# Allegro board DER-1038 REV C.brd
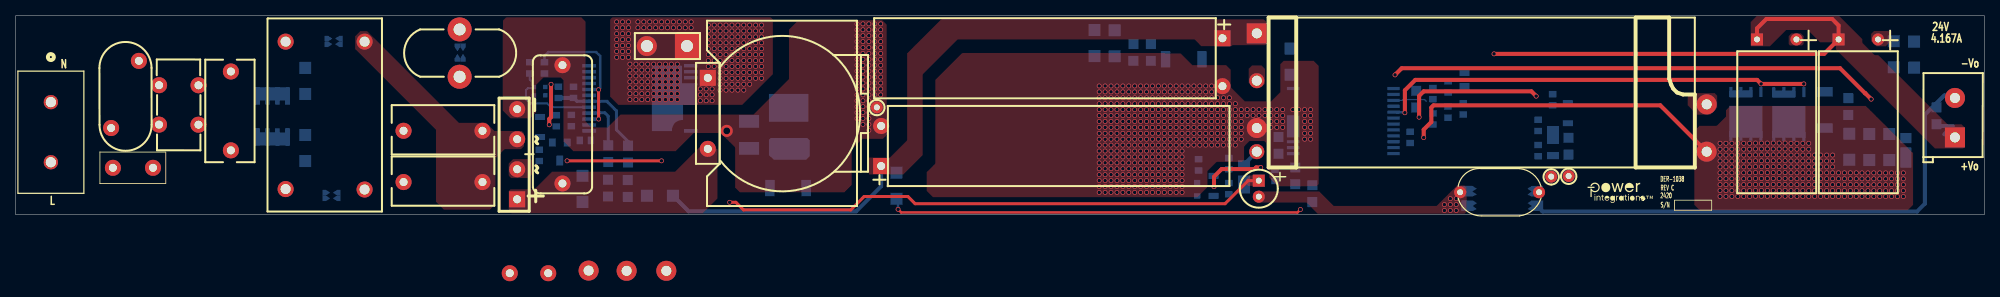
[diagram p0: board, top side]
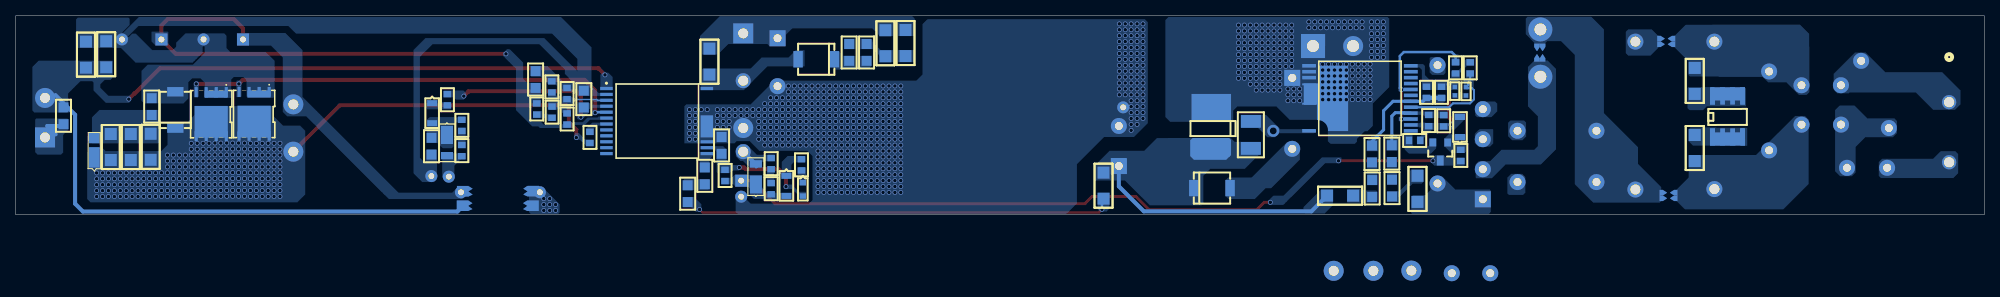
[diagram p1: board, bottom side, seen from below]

Outline 249.4 x 25.2 mm; copper layers: TOP, BOTTOM. Coordinates in mm from the lower left corner of the outline.
Outline path: 0,25.2 0,0 249.4,0 249.4,25.2 0,25.2

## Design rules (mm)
constraint set DEFAULT: min track width 0.508

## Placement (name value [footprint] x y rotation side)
BR1  UD4KB100-BP  [PIDAXBRIDGED3K]  63.53 1.93 90 top
C1  0.15 uF  [PINPXCAPRAD13X6MM040]  27.25 18.14 270 top
C2  0.15 uF  [PINPXCAPRAD13X6MM040]  59.13 10.62 180 top
C3  1 uF  [PINPCAPRAD17P5X7P8X15MMLS]  69.27 3.94 90 top
C4  1 uF  [PISMC0603]  72.87 9.4 180 bottom
C5  470 pF  [PISMC0603]  70.38 12.62 270 bottom
C6  1 uF  [PISMC0603]  66.98 19.3 270 bottom
C7  0.1 uF  [PISMC0603]  65.13 17.88 90 bottom
C8  1 uF  [PISMR0402]  67.08 15.11 90 bottom
C9  470 pF  [PISMC0603]  70.66 14.78 90 bottom
C10  22 nF  [PISMC1210]  92.91 8.38 90 bottom
C11  33 uF  [PIPOLCAPD395LS200D0401705LH]  153.59 22.35 270 top
C12  33 uF  [PIPOLCAPD395LS200D0401705LH#2]  108.94 6.15 90 top
C13  NC  [PISMC0603]  153.7 2.57 90 bottom
C14  22 uf  [PI_POLCAP_D200_LS80_D030]  157.49 4.29 270 top
C15  2.2 nF  [PISMC1206]  139.22 23.37 270 bottom
C16  0.47 uF  [PISMC0805]  159.98 7.7 90 bottom
C18  2.2 uF  [PISMC0805]  177.43 13.56 90 bottom
C19  2200 pF  [PINPCAPRAD11X6MMD030]  183 2.82 0 top
C20  NC  [PISMC0603]  192.89 7.39 90 bottom
C21  2200 pf  [PISMC0805]  232.18 14.76 270 bottom
C22  10 uF  [PISMC0805]  196.72 9.73 270 bottom
C23  22 nF  [PISMC0603]  181.46 12.27 90 bottom
C24  1 nF  [PISMC0603]  179.55 14.63 90 bottom
C25  680 uF  [PIPOLCAPCLYD10MMD30]  225.61 22.2 180 top
C26  680 uF  [PIPOLCAPCLYD10MMD30]  235.95 22.2 180 top
C27  2.2 uF  [PISMC0805]  243.36 11.46 90 bottom
C28  0.15 uF  [PINPXCAPRAD13X6MM040]  59.13 4.11 180 top
C29  47 pF  [PISMC1206]  161.52 21.03 270 bottom
C30  2.2 uF  [PISMC0805]  183.54 18.19 270 bottom
D1  LXA03D530  [PI_SM_DIODE_SO8C]  95.81 13.39 0 bottom
D3  STTH208UFY  [PISMDO221AA]  97.84 3.35 180 bottom
D4  DFLR1200-7  [PISMDDFLR120012]  155.63 3.78 270 bottom
D5  BAV19WS  [PISMSOD323]  151.76 4.9 270 bottom
D6  GS1MFL-TP  [PISMDO221AA]  147.98 19.68 0 bottom
D8  SS10200HE_R1_00001  [PI_SM_SOD-123HE]  239.47 7.24 90 bottom
D9  DFLR1200-7  [PISMDDFLR120012]  194.77 10.11 90 bottom
D10  BAV19WS  [PISMSOD323]  196.65 14.12 270 bottom
F1  3.15 A  [PI_RST_MICROFUSE]  12.31 5.92 0 top
FL1  Hole_30mils  [PI_HOLE_30MIL]  194.54 4.8 0 top
FL2  Hole_30mils  [PI_HOLE_30MIL]  196.75 4.88 0 top
FL3  Hole_30mils  [PI_HOLE_30MIL]  109.09 13.59 0 top
J1  TERMINAL BLOCK  [PI_TERM_BLOCK_2PIN_LS200]  245.69 9.78 0 top
J2  CON2  [CONN_1707027_PXC]  4.45 14.25 270 top
L1  330 uH  [PI_4P_LS5W4P8XD11P5MMD40]  20.65 13.89 269.9 top
L2  15 mH  [PIIND4P965X571LS736X394D040]  44.2 21.92 270 top
L3  68 uH  [PI2P14DX6MMWD060]  56.24 23.47 270 top
NOREF  -  []  249.4 0 90 top
NOREF#2  -  []  -150.23 13.59 0 top
NOREF#3  -  []  0 25.2 0 top
NOREF#4  -  []  198.73 3.28 0 top
NOREF#5  -  []  -232.77 -144.45 0 top
NOREF#6  -  [unnamed#2]  188.31 2.95 179.9 bottom
NOREF#7  -  [unnamed#2]  188.33 1.12 180 bottom
Q1  MMBT4401LT1G  [PISMSOT23123_1]  68.91 8.03 0 bottom
Q2  SRT15N110LD56TR-G  [PISMPQFN5X6B]  222.73 15.52 0 bottom
Q3  SRT15N110LD56TR-G  [PISMPQFN5X6B]  217.3 15.54 0 bottom
R1  510 k  [PISMR1206]  36.68 6.78 90 bottom
R2  510 k  [PISMR1206]  36.68 15.29 90 bottom
R3  100 K  [PISMR0603]  66.32 6.78 90 bottom
R4  6.8 M  [PISMR1206]  71.81 4.9 270 bottom
R5  4.7 M  [PISMR0805]  75.03 4.42 270 bottom
R6  4.7 M  [PISMR0805]  75.06 6.65 90 bottom
R7  154 k  [PISMR0603]  68.48 12.6 270 bottom
R8  30.1 k  [PISMR0402]  65.66 16.15 270 bottom
R9  6.8 M  [PISMR1206]  83.26 2.39 180 bottom
R10  4.7 M  [PISMR0805]  77.55 2.24 90 bottom
R11  4.7 M  [PISMR0805]  77.57 8.74 270 bottom
R12  158 k  [PISMR0603]  68.76 16.21 270 bottom
R13  NC  [PISMR0603]  153.7 5.74 90 bottom
R14  5.1 k  [PISMR0603]  159.54 4.24 90 bottom
R15  100  [PISMR0603]  149.86 5.59 90 bottom
R16  500 k  [PISMR1206]  136.68 23.39 270 bottom
R17  15  [PISMR0805]  143.81 19.48 90 bottom
R19  15  [PISMR0805]  141.6 19.48 90 bottom
R20  1.6 M  [PISMR1206]  111.58 5.31 270 bottom
R21  1.2 M  [PISMR0805]  164.27 1.57 90 bottom
R22  1.2 M  [PISMR0805]  162.1 3.84 90 bottom
R23  300  [PISMR0603]  176.66 9.07 90 bottom
R24  15  [PISMR1206]  234.82 10.21 270 bottom
R25  15  [PISMR1206]  232.31 10.24 270 bottom
R26  NC  [PISMR0603]  192.89 10.59 90 bottom
R27  4.7 k  [PISMR0603]  183.39 14.1 270 bottom
R28  1.2 k  [PISMR0603]  194.72 13.84 90 bottom
R29  100 K  [PISMR0603]  179.55 11.4 90 bottom
R30  5.49 k  [PISMR0603]  181.48 15.47 90 bottom
R31  0.01  [PISMR1206]  240.51 21.92 270 bottom
R32  0.01  [PISMR1206]  237.95 21.97 270 bottom
R33  15  [PISMR1206]  237.36 10.21 270 bottom
RV1  320 Vac  [PIDISC500X225LS335X140040]  15.6 19.48 270.1 top
T1  ATQ23.2/11.6  [PI_BOBBIN_ATQ23_V_4PB]  97.08 12.83 0 top
T2  EDR4110  [PI_BOBBIN_EDR4110_9P_6X3]  185.73 15.47 0 top
TAB1  CON2  [PI_CONN_QC_TAB_2PIN_LS200]  85.04 21.36 90 top
U1  CAP200DG *  [PI_IC_SMD_SO8_CAPZERO]  34.42 9.83 179.9 bottom
U2  PFS7624C  [PI_IC_INSOP24B]  79.1 14.73 0 bottom
U3  INN4276C-H182  [PI_IC_INSOP_24D_IPC]  174.56 15.98 180 bottom
VR1  BZX384-B13,115  [PISMSOD323]  66.42 9.83 90 bottom
VR2  DZ2S300M0L  [PI_SM_D_SSMINI2P]  149.68 4.04 270 bottom
VR3  SMA6F100A-M3/H  [PISMDO221AA]  229.18 13.26 90 bottom

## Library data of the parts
BR1 = DISCRETE BRIDGE_+~~-: alternate symbols: (pidaxbridgeD3K_horz)
C1 C2 C28 = CAP NP: alternate symbols: (pinpxcaprad13x6x12Hmm040); room: 1
C3 = CAP NP: alternate symbols: (pinpcaprad17p5x15mmLSH)
C4 C6 = CAP NP: alternate symbols: (Unisem_RMCF0603UL); room: 2
C5 C9 = CAP NP: room: 2
C7 = CAP NP: alternate symbols: (Unisem_RMCF0603UL,cc0603); room: 2
C8 = CAP NP: alternate symbols: (pismr0402_1); room: 2
C10 C19 C29 = CAP NP
C11 C12 C14 = CAP POL
C13 C20 = CAP NP: alternate symbols: (Unisem_RMCF0603UL)
C15 = CAP NP: alternate symbols: (CAP_3216_TDK); room: 3
C16 = CAP NP: alternate symbols: (Unisem_RMCF0805UL); room: 3
C18 C30 = CAP NP: room: 4
C21 = CAP NP: alternate symbols: (Unisem_RMCF0805UL); room: 4
C22 C27 = CAP NP: alternate symbols: (Unisem_RMCF0805UL)
C23 C24 = CAP NP: alternate symbols: (Unisem_RMCF0603UL); room: 4
C25 C26 = CAP POL: alternate symbols: (pipolcapclyd10x18mmD30H); room: 4
D1 = DIODE_A1K8
D3 = DIODE: room: 2
D4-D6 D9 D10 = DIODE
D8 = DIODE SCHOTTKY
F1 = FUSE: alternate symbols: (pirstmicrofusehoz); room: 1
FL1-FL3 = FlyingLead: room: 3
J1 = CON2
J2 = CON2: User Part Number: PN; Tolerance: TOL
L1 = TORRID 4P_14_23
L2 = INDUCTOR_4P_1-2_4-3
L3 = INDUCTOR: room: 1
Q1 = NPN_BEC: room: 2
Q2 Q3 = FET_N_SGD_123_4_5678
R1 R2 R16 R31 R32 = R
R3 R4 R8 R9 = R: room: 2
R5 R6 R10 R11 = R: alternate symbols: (Unisem_RMCF0805UL); room: 2
R7 R12 = R: alternate symbols: (Unisem_RMCF0603UL); room: 2
R13 R15 R26 = R: alternate symbols: (Unisem_RMCF0603UL)
R14 = R: alternate symbols: (Unisem_RMCF0603UL); room: 3
R17 R19 = R: alternate symbols: (Unisem_RMCF0805UL)
R20 = R: room: 3
R21 R22 = R: alternate symbols: (Unisem_RMCF0805UL); room: 3
R23 R27 R28 R30 = R: alternate symbols: (Unisem_RMCF0603UL); room: 4
R24 R25 R29 R33 = R: room: 4
RV1 = VARISTOR: alternate symbols: (pi_rad450x550ls300d040_h); room: 1
T1 = BATQ23.2_4P/GENERIC
T2 = BEQ20_9P
TAB1 = CON1_2P_TAB
U1 = CAPZero
U2 = HIPERPFS-4-inSOP24B
U3 = INNO4-QR: alternate symbols: (pi_ic_insop_24d)
VR1 = DIODE_ZENER: room: 2
VR2 VR3 = DIODE_ZENER

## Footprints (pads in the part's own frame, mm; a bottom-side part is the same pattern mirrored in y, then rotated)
CONN_1707027_PXC
  round 1.803 hole 1.295: 1(0,0) 2(7.62,0)
PI2P14DX6MMWD060
  round 3.048 hole 1.524: 1(0,0) 2(6,0)
PI_4P_LS5W4P8XD11P5MMD40
  round 2.032 hole 1.016: 1(-2.5,-2.5) 2(2.5,-2.5) 3(2.5,2.5) 4(-2.5,2.5)
PI_BOBBIN_ATQ23_V_4PB
  rect 2.032x2.032 hole 1.016: 1(-9.4,4.5)
  round 2.032 hole 1.016: 2(-29.616,-20.269) 3(-34.493,-20.269) 4(-9.4,-4.5)
PI_BOBBIN_EDR4110_9P_6X3
  rect 2.54x2.54 hole 1.27: 1(-28.5,7.5)
  round 2.54 hole 1.27: 2(-108.34,-22.606) 4(-113.157,-22.581) 5(-28.5,-4.5) 7(28.5,-7.5) 8(-103.311,-22.606) 9(28.5,-1.5)
  round 1.905 hole 1.27: 3(-28.5,1.5) 6(-28.5,-7.5)
PI_CONN_QC_TAB_2PIN_LS200
  rect 3.048x3.048 hole 1.524: 1(0,0)
  round 2.54 hole 1.524: 2(0,5.08)
PI_HOLE_30MIL
  round 1.524 hole 0.762: 1(0,0)
PI_IC_INSOP24B
  rect 1.75x0.45 smd: 1(-6.445,4.125) 2(-6.445,3.375) 3(-6.445,2.625) 4(-6.445,1.875) 5(-6.445,1.125) 6(-6.445,0.375) 7(-6.445,-0.375) 8(-6.445,-1.125) 9(-6.445,-1.875) 10(-6.445,-2.625) 11(-6.445,-3.375) 12(-6.445,-4.125) 13(6.445,-4.125) 14(6.445,-3.375) 15(6.445,-2.625) 24(6.445,4.125)
  custom 0.437x0.437 smd: 16(6.445,-0.545)
PI_IC_INSOP_24D_IPC
  rect 1.58x0.409 smd: 1(0,0) 2(0,-0.75) 3(0,-1.5) 4(0,-2.25) 5(0,-3) 6(0,-3.75) 7(0,-4.5) 8(0,-5.25) 9(0,-6) 10(0,-6.75) 11(0,-7.5) 12(0,-8.25) 13(12.72,-8.25) 14(12.72,-7.5) 15(12.72,-6.75) 24(12.72,0)
  rect 1.58x2.809 smd: 16(12.72,-4.8)
PI_IC_SMD_SO8_CAPZERO
  rect 0.599x2.2 smd: 1(0,0) 2(1.27,0) 3(2.54,0) 4(3.81,0) 5(3.81,5.199) 6(2.54,5.199) 7(1.27,5.199) 8(0,5.199)
PI_POLCAP_D200_LS80_D030
  rect 1.524x1.524 hole 0.762: 1(0,0)
  round 1.524 hole 0.762: 2(2.032,0)
PI_RST_MICROFUSE
  round 2.032 hole 1.016: 1(0,0) 2(5.08,0)
PI_SM_D_SSMINI2P
  rect 0.699x0.8 smd: 1(0,0) 2(1.7,0)
PI_SM_DIODE_SO8C
  oval 0.635x2.388 smd: (1.27,0) (1.27,4.902) (2.54,4.902) (3.81,0) (3.81,4.902) 8(0,4.902)
  rect 0.635x2.388 smd: 1(0,0)
PI_SM_SOD-123HE
  rect 2.601x1.399 smd: 1(0,0)
  rect 1.301x1.399 smd: 2(2.45,0)
PI_TERM_BLOCK_2PIN_LS200
  rect 2.54x2.54 hole 1.27: 1(0,0)
  round 2.54 hole 1.27: 2(0,5.001)
PIDAXBRIDGED3K
  rect 2.032x2.032 hole 1.016: 1(0,0)
  round 2.032 hole 1.016: 2(3.81,0) 3(7.62,0) 4(11.43,0)
PIDISC500X225LS335X140040
  round 2.032 hole 1.016: 1(0,0) 2(8.509,-3.531)
PIIND4P965X571LS736X394D040
  round 2.032 hole 1.27: 1(18.694,-10.008) 2(18.75,0) 3(0,0) 4(0,-10.008)
PINPCAPRAD11X6MMD030
  round 1.524 hole 0.762: 1(0,0) 2(10,0)
PINPCAPRAD17P5X7P8X15MMLS
  round 2.032 hole 1.016: 1(0,0) 2(15,0)
PINPXCAPRAD13X6MM040
  round 2.032 hole 1.016: 1(0,0) 2(10,0)
PIPOLCAPCLYD10MMD30
  rect 1.524x1.524 hole 0.762: 1(5,0)
  round 1.524 hole 0.762: 2(0,0)
PIPOLCAPD395LS200D0401705LH
  rect 2.032x2.032 hole 1.016: 1(0,-0.7)
  round 2.032 hole 1.016: 2(6.08,-0.7)
PIPOLCAPD395LS200D0401705LH#2
  rect 2.032x2.032 hole 1.016: 1(0,-0.7)
  round 2.032 hole 1.016: 2(5.08,-0.7)
PISMC0603
  rect 0.813x0.965 smd: 1(0,0) 2(1.422,0)
PISMC0805
  rect 1.27x1.27 smd: 1(0,0) 2(2.134,0)
PISMC1206
  rect 1.524x1.524 smd: 1(0,0) 2(3.302,0)
PISMC1210
  rect 1.626x2.54 smd: 1(0,0) 2(3.429,0)
PISMDDFLR120012
  rect 2.286x1.524 smd: 1(-0.025,0)
  rect 0.914x1.524 smd: 2(-2.642,0)
PISMDO221AA
  rect 1.2x2.07 smd: 1(-2.3,0) 2(2.3,0)
PISMPQFN5X6B
  rect 0.406x1.27 smd: 1(0,0) 2(1.27,0) 3(2.54,0) 4(3.81,0)
  rect 0.406x1.219 smd: 5(3.81,5.588) 6(2.54,5.588) 7(1.27,5.588) 8(0,5.588)
PISMR0402
  rect 0.559x0.559 smd: 1(0,0) 2(1.067,0)
PISMR0603
  rect 0.813x0.965 smd: 1(0,0) 2(1.422,0)
PISMR0805
  rect 1.27x1.27 smd: 1(0,0) 2(2.134,0)
PISMR1206
  rect 1.524x1.524 smd: 1(0,0) 2(3.302,0)
PISMSOD323
  rect 0.762x1.27 smd: 1(0,0) 2(2.54,0)
PISMSOT23123_1
  rect 0.864x1.016 smd: 1(-0.93,-1.1) 2(0.95,-1.1)
  rect 0.864x1.27 smd: 3(0.01,1.186)
unnamed#2
  custom 0.338x0.338 smd: 1(-4.2,0) 2(4.2,0)

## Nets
GND: C18.2 C21.1 C22.2 C24.2 C25.2 C26.2 C30.1 FL2.1 Q2.1 Q2.2 Q2.3(S3) Q3.1 Q3.2 Q3.3(S3) R30.2 R31.1 R32.1 U3.2 VR3.2
VCCP: C13.1 C14.1 D4.1 D5.2 Q1.3 R3.1 R14.1
BPS: C18.1 R28.2 U3.4
N13420620: C10.1 C11.1 C12.1 C15.1 C29.1 D1.8(K) D3.1 R9.1 R16.1 R20.1 T2.1
N13420648: BR1.4 C3.2 C10.2 C11.2 C12.2 C14.2 C16.2 C19.1 FL3.1 T2.5 U2.24 U3.15 U3.16
N13420656: C19.2 C25.1 C26.1 C27.1 C30.2 J1.1 R27.1 R29.1 T2.9 U3.6
N13421012: C23.2 C24.1 R29.2 R30.1 U3.3
N13421042: C23.1 R27.2
N13421702: C21.2 D8.2 R24.1 R25.1 R33.1
N13421894: D8.1 Q2.5 Q2.6 Q2.7 Q2.8 Q3.5 Q3.6 Q3.7 Q3.8 R23.1 R24.2 R25.2 R33.2 T2.7 VR3.1
N13422446: Q2.4 Q3.4 U3.5
N13423706: C16.1 R14.2 U3.14 VR2.2
N13423710: C20.1 D9.2 FL1.1
N13423714: C22.1 D9.1 D10.2 R26.2
N13440082: D10.1 R28.1
N13449363: D4.2 R13.2 T2.6
N13473411: R15.1 VR2.1
N13473415: D5.1 R15.2
N13513324: C27.2 J1.2 R31.2 R32.2 U3.1
N13515268: C13.2 R13.1
N13515819: C20.2 R26.1
N13523750: R20.2 R21.1
N13523772: R21.2 R22.1
N13523865: R22.2 U3.13
N13911889: C15.2 R16.2 R17.2 R19.2
N13911953: D6.1 R17.1 R19.1
N13912909: C29.2 D6.2 T2.3 U3.24
N13916087: R23.2 U3.7
N13925544: BR1.2 L3.2
N13925608: BR1.3(AC2) C2.1 C28.1 L2.3
N13925722: C2.2 C28.2 L2.2 L3.1
N13925782: C1.2 L1.3 L2.1 R1.1
N13925794: C1.1 L1.4 L2.4 R2.2
N13925904: R1.2 U1.1 U1.2 U1.3 U1.4
N13925908: R2.1 U1.5 U1.7 U1.8(NC8)
N13925956: F1.2 L1.2 RV1.2
N13925960: J2.1 L1.1 RV1.1
N13926028: F1.1 J2.2
N13967468: BR1.1 C3.1 D3.2 R4.2 T1.4
N13967702: R9.2 R10.1
N13967706: R4.1 R5.2
N13967710: C9.1 R11.1 R12.2 U2.6
N13967734: C6.1 U2.3 U2.8
N13967764: C7.1 R8.1 U2.5
N13967780: R5.1 R6.1
N13967788: C5.1 R6.2 R7.1 U2.4
N13967796: R10.2 R11.2
N13967854: C4.1 Q1.2(EMITTER) U2.1(VCC)
N13967858: C4.2 C5.2 C6.2 C7.2 C8.2 C9.2 R7.2 R12.1 U2.2 U2.12 VR1.2
N13968000: C8.1 R8.2
N13968020: Q1.1 R3.2 VR1.1
N13971397: D1.1 T1.1 TAB1.1 TAB1.2 U2.16

Pads without a net: NOREF#6 1 2; NOREF#7 1 2; T1 2 3; T2 2 4 8; U1 6; U2 7 9 10 11 13 14 15; U3 8 9 10 11 12

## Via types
v1: diameter 0.61, hole 0.457, TOP to BOTTOM, 995 vias
v2: diameter 1.524, hole 0.889, TOP to BOTTOM, 1 via

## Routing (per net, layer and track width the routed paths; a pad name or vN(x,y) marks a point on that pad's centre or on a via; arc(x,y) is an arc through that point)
VCCP: length 81.7
  TOP w0.381: v1(90.45,1.55) 91.24,1.55 92.2,0.58 105.79,0.58 107.49,2.29 113.03,2.29 113.94,1.37 153.21,1.37 156.13,4.29 C14.1 ; v1(81.81,6.81) v1(69.85,6.81)
BPS: length 18
  TOP w0.508: v1(177.8,12.34) 177.8,15.04 178.38,15.62 192.02,15.62 v1(192.63,15.01)
N13420620: length 31.1
  BOTTOM w0.508: C12.1 109.64,3.57 106.48,0.41 85.24,0.41 R9.1
N13420648:
  vias: v1(106.58,24.17) v1(106.58,23.42) v1(106.58,22.67) v1(106.58,21.92) v1(106.58,21.17) v1(106.58,20.42) v1(106.58,19.67) v1(106.58,18.92) v1(106.58,18.17) v1(106.58,17.42) v1(106.58,16.67) v1(106.58,15.92) v1(106.58,15.17) v1(106.58,14.42) v1(106.58,13.67) v1(106.58,12.92) v1(106.58,12.17) v1(107.33,24.17) v1(107.33,23.42) v1(107.33,22.67) v1(107.33,21.92) v1(107.33,21.17) v1(107.33,20.42) v1(107.33,19.67) v1(107.33,18.92) v1(107.33,18.17) v1(107.33,17.42) v1(107.33,16.67) v1(107.33,15.92) v1(107.33,15.17) v1(107.33,14.42) v1(107.33,13.67) v1(107.33,12.92) v1(107.33,12.17) v1(107.33,11.42) v1(108.08,24.17) v1(108.08,23.42) v1(108.08,22.67) v1(108.08,21.92) v1(108.08,21.17) v1(108.08,20.42) v1(108.08,19.67) v1(108.08,18.92) v1(108.08,18.17) v1(108.08,17.42) v1(108.08,16.67) v1(108.08,15.92) v1(108.08,15.17) v1(108.08,14.42) v1(108.08,13.67) v1(108.08,12.92) v1(108.08,12.17) v1(108.08,11.42) v1(108.08,10.67) v1(108.83,24.17) v1(108.83,23.42) v1(108.83,22.67) v1(108.83,21.92) v1(108.83,21.17) v1(108.83,20.42) v1(108.83,19.67) v1(108.83,18.92) v1(108.83,18.17) v1(108.83,17.42) v1(108.83,16.67) v1(108.83,15.92) v1(108.83,15.17) v1(109.58,24.17) v1(109.58,23.42) v1(109.58,22.67) v1(109.58,21.92) v1(109.58,21.17) v1(109.58,20.42) v1(109.58,19.67) v1(109.58,18.92) v1(109.58,18.17) v1(109.58,17.42) v1(109.58,16.67) v1(109.58,15.92) v1(109.58,15.17) v1(137.27,16.3) v1(137.27,15.55) v1(137.27,14.8) v1(137.27,14.05) v1(137.27,13.3) v1(137.27,12.55) v1(137.27,11.8) v1(137.27,11.05) v1(137.27,10.3) v1(137.27,9.55) v1(137.27,8.8) v1(137.27,8.05) v1(137.27,7.3) v1(137.27,6.55) v1(137.27,5.8) v1(137.27,5.05) v1(137.27,4.3) v1(137.27,3.55) v1(137.27,2.8) v1(138.02,16.3) v1(138.02,15.55) v1(138.02,14.8) v1(138.02,14.05) v1(138.02,13.3) v1(138.02,12.55) v1(138.02,11.8) v1(138.02,11.05) v1(138.02,10.3) v1(138.02,9.55) v1(138.02,8.8) v1(138.02,8.05) v1(138.02,7.3) v1(138.02,6.55) v1(138.02,5.8) v1(138.02,5.05) v1(138.02,4.3) v1(138.02,3.55) v1(138.02,2.8) v1(138.77,16.3) v1(138.77,15.55) v1(138.77,14.8) v1(138.77,14.05) v1(138.77,13.3) v1(138.77,12.55) v1(138.77,11.8) v1(138.77,11.05) v1(138.77,10.3) v1(138.77,9.55) v1(138.77,8.8) v1(138.77,8.05) v1(138.77,7.3) v1(138.77,6.55) v1(138.77,5.8) v1(138.77,5.05) v1(138.77,4.3) v1(138.77,3.55) v1(138.77,2.8) v1(139.52,16.3) v1(139.52,15.55) v1(139.52,14.8) v1(139.52,14.05) v1(139.52,13.3) v1(139.52,12.55) v1(139.52,11.8) v1(139.52,11.05) v1(139.52,10.3) v1(139.52,9.55) v1(139.52,8.8) v1(139.52,8.05) v1(139.52,7.3) v1(139.52,6.55) v1(139.52,5.8) v1(139.52,5.05) v1(139.52,4.3) v1(139.52,3.55) v1(139.52,2.8) v1(140.27,16.3) v1(140.27,15.55) v1(140.27,14.8) v1(140.27,14.05) v1(140.27,13.3) v1(140.27,12.55) v1(140.27,11.8) v1(140.27,11.05) v1(140.27,10.3) v1(140.27,9.55) v1(140.27,8.8) v1(140.27,8.05) v1(140.27,7.3) v1(140.27,6.55) v1(140.27,5.8) v1(140.27,5.05) v1(140.27,4.3) v1(140.27,3.55) v1(140.27,2.8) v1(141.02,16.3) v1(141.02,15.55) v1(141.02,14.8) v1(141.02,14.05) v1(141.02,13.3) v1(141.02,12.55) v1(141.02,11.8) v1(141.02,11.05) v1(141.02,10.3) v1(141.02,9.55) v1(141.02,8.8) v1(141.02,8.05) v1(141.02,7.3) v1(141.02,6.55) v1(141.02,5.8) v1(141.02,5.05) v1(141.02,4.3) v1(141.02,3.55) v1(141.02,2.8) v1(141.77,16.3) v1(141.77,15.55) v1(141.77,14.8) v1(141.77,14.05) v1(141.77,13.3) v1(141.77,12.55) v1(141.77,11.8) v1(141.77,11.05) v1(141.77,10.3) v1(141.77,9.55) v1(141.77,8.8) v1(141.77,8.05) v1(141.77,7.3) v1(141.77,6.55) v1(141.77,5.8) v1(141.77,5.05) v1(141.77,4.3) v1(141.77,3.55) v1(141.77,2.8) v1(142.52,16.3) v1(142.52,15.55) v1(142.52,14.8) v1(142.52,14.05) v1(142.52,13.3) v1(142.52,12.55) v1(142.52,11.8) v1(142.52,11.05) v1(142.52,10.3) v1(142.52,9.55) v1(142.52,8.8) v1(142.52,8.05) v1(142.52,7.3) v1(142.52,6.55) v1(142.52,5.8) v1(142.52,5.05) v1(142.52,4.3) v1(142.52,3.55) v1(142.52,2.8) v1(143.27,16.3) v1(143.27,15.55) v1(143.27,14.8) v1(143.27,14.05) v1(143.27,13.3) v1(143.27,12.55) v1(143.27,11.8) v1(143.27,11.05) v1(143.27,10.3) v1(143.27,9.55) v1(143.27,8.8) v1(143.27,8.05) v1(143.27,7.3) v1(143.27,6.55) v1(143.27,5.8) v1(143.27,5.05) v1(143.27,4.3) v1(143.27,3.55) v1(143.27,2.8) v1(144.02,16.3) v1(144.02,15.55) v1(144.02,14.8) v1(144.02,14.05) v1(144.02,13.3) v1(144.02,12.55) v1(144.02,11.8) v1(144.02,11.05) v1(144.02,10.3) v1(144.02,9.55) v1(144.02,8.8) v1(144.02,8.05) v1(144.02,7.3) v1(144.02,6.55) v1(144.02,5.8) v1(144.02,5.05) v1(144.02,4.3) v1(144.02,3.55) v1(144.02,2.8) v1(144.77,16.3) v1(144.77,15.55) v1(144.77,14.8) v1(144.77,14.05) v1(144.77,13.3) v1(144.77,12.55) v1(144.77,11.8) v1(144.77,11.05) v1(144.77,10.3) v1(144.77,9.55) v1(144.77,8.8) v1(144.77,8.05) v1(144.77,7.3) v1(144.77,6.55) v1(144.77,5.8) v1(144.77,5.05) v1(144.77,4.3) v1(144.77,3.55) v1(144.77,2.8) v1(145.52,16.3) v1(145.52,15.55) v1(145.52,14.8) v1(145.52,14.05) v1(145.52,13.3) v1(145.52,12.55) v1(145.52,11.8) v1(145.52,11.05) v1(145.52,10.3) v1(145.52,9.55) v1(145.52,8.8) v1(145.52,8.05) v1(145.52,7.3) v1(145.52,6.55) v1(145.52,5.8) v1(145.52,5.05) v1(145.52,4.3) v1(145.52,3.55) v1(145.52,2.8) v1(146.27,16.3) v1(146.27,15.55) v1(146.27,14.8) v1(146.27,14.05) v1(146.27,13.3) v1(146.27,12.55) v1(146.27,11.8) v1(146.27,11.05) v1(146.27,10.3) v1(146.27,9.55) v1(146.27,8.8) v1(146.27,8.05) v1(146.27,7.3) v1(146.27,6.55) v1(146.27,5.8) v1(146.27,5.05) v1(146.27,4.3) v1(146.27,3.55) v1(146.27,2.8) v1(147.02,16.3) v1(147.02,15.55) v1(147.02,14.8) v1(147.02,14.05) v1(147.02,13.3) v1(147.02,12.55) v1(147.02,11.8) v1(147.02,11.05) v1(147.02,10.3) v1(147.02,9.55) v1(147.02,8.8) v1(147.02,8.05) v1(147.02,7.3) v1(147.02,6.55) v1(147.02,5.8) v1(147.02,5.05) v1(147.02,4.3) v1(147.02,3.55) v1(147.02,2.8) v1(147.77,16.3) v1(147.77,15.55) v1(147.77,14.8) v1(147.77,14.05) v1(147.77,13.3) v1(147.77,12.55) v1(147.77,11.8) v1(147.77,11.05) v1(147.77,10.3) v1(147.77,9.55) v1(147.77,8.8) v1(147.77,8.05) v1(147.77,7.3) v1(147.77,6.55) v1(147.77,5.8) v1(147.77,5.05) v1(147.77,4.3) v1(147.77,3.55) v1(147.77,2.8) v1(148.52,16.3) v1(148.52,15.55) v1(148.52,14.8) v1(148.52,14.05) v1(148.52,13.3) v1(148.52,12.55) v1(148.52,11.8) v1(148.52,11.05) v1(148.52,10.3) v1(148.52,9.55) v1(148.52,8.8) v1(149.27,16.3) v1(149.27,15.55) v1(149.27,14.8) v1(149.27,14.05) v1(149.27,13.3) v1(149.27,12.55) v1(149.27,11.8) v1(149.27,11.05) v1(149.27,10.3) v1(149.27,9.55) v1(149.27,8.8) v1(150.02,16.3) v1(150.02,15.55) v1(150.02,14.8) v1(150.02,14.05) v1(150.02,13.3) v1(150.02,12.55) v1(150.02,11.8) v1(150.02,11.05) v1(150.02,10.3) v1(150.02,9.55) v1(150.02,8.8) v1(150.77,16.3) v1(150.77,15.55) v1(150.77,14.8) v1(150.77,14.05) v1(150.77,13.3) v1(150.77,12.55) v1(150.77,11.8) v1(150.77,11.05) v1(150.77,10.3) v1(150.77,9.55) v1(150.77,8.8) v1(151.52,16.3) v1(151.52,15.55) v1(151.52,14.8) v1(151.52,14.05) v1(151.52,13.3) v1(151.52,12.55) v1(151.52,11.8) v1(151.52,11.05) v1(151.52,10.3) v1(151.52,9.55) v1(151.52,8.8) v1(152.27,14.8) v1(152.27,14.05) v1(152.27,13.3) v1(152.27,12.55) v1(152.27,11.8) v1(152.27,11.05) v1(152.27,10.3) v1(152.27,9.55) v1(152.27,8.8) v1(153.02,14.8) v1(153.02,14.05) v1(153.02,13.3) v1(153.02,12.55) v1(153.02,11.8) v1(153.02,11.05) v1(153.02,10.3) v1(153.02,9.55) v1(153.02,8.8) v1(153.77,14.8) v1(153.77,14.05) v1(153.77,13.3) v1(153.77,12.55) v1(153.77,11.8) v1(153.77,11.05) v1(153.77,10.3) v1(153.77,9.55) v1(153.77,8.8) v1(154.52,14.05) v1(154.52,13.3) v1(154.52,12.55) v1(154.52,11.8) v1(154.52,11.05) v1(154.52,10.3) v1(154.52,9.55) v1(154.52,8.8) v1(155.27,13.3) v1(155.27,12.55) v1(155.27,11.8) v1(155.27,11.05) v1(155.27,10.3) v1(155.27,9.55) v1(156.02,13.3) v1(156.02,12.55) v1(156.77,13.3) v1(156.77,12.55) v1(157.52,13.3) v1(157.52,12.55) v1(158.27,13.3) v1(158.27,12.55) v1(159.02,13.3) v1(159.02,12.55) v1(159.02,11.8) v1(159.02,11.05) v1(159.77,13.3) v1(159.77,12.55) v1(159.77,11.8) v1(159.77,11.05) v1(160.52,13.3) v1(160.52,12.55) v1(160.52,11.8) v1(160.52,11.05) v1(161.8,13.3) v1(162.55,13.3) v1(163.3,13.3) v1(163.3,12.55) v1(163.3,11.8) v1(163.3,11.05) v1(163.3,10.3) v1(163.3,9.55) v1(164.05,13.3) v1(164.05,12.55) v1(164.05,11.8) v1(164.05,11.05) v1(164.05,10.3) v1(164.05,9.55) v1(181,1.26) v1(181,0.51) v1(181.75,2.01) v1(181.75,1.26) v1(181.75,0.51) v1(182.5,2.01) v1(182.5,1.26) v1(182.5,0.51) v2(90.08,10.61)
N13420656: length 62.4
  TOP w0.508: C25.1 220.61,23.61 221.79,24.79 230.13,24.79 230.95,23.97 C26.1 229.12,20.37 v1(187.29,20.37)
  BOTTOM w0.508: C27.1 243.59,11.23 245.41,11.23 244.35,10.16
N13421012: length 4.3
  BOTTOM w0.156: U3.3 175.68,14.48 175.79,14.58 178.49,14.58 178.72,14.35
N13421042: length 0.2
  BOTTOM w0.305: 183.31,12.67 R27.2 ; C23.1 181.53,12.19
N13421894: length 41.6
  TOP w0.508: T2.7 208.36,13.84 179.63,13.84 179.35,13.56 179.35,11.73 178.38,10.77 v1(178.38,9.75)
  vias: v1(215.93,9.04) v1(215.93,8.29) v1(215.93,7.54) v1(215.93,6.79) v1(215.93,6.04) v1(215.93,5.29) v1(215.93,4.54) v1(215.93,3.79) v1(215.93,3.04) v1(215.93,2.29) v1(216.68,9.04) v1(216.68,8.29) v1(216.68,7.54) v1(216.68,6.79) v1(216.68,6.04) v1(216.68,5.29) v1(216.68,4.54) v1(216.68,3.79) v1(216.68,3.04) v1(216.68,2.29) v1(217.43,9.04) v1(217.43,8.29) v1(217.43,7.54) v1(217.43,6.79) v1(217.43,6.04) v1(217.43,5.29) v1(217.43,4.54) v1(217.43,3.79) v1(217.43,3.04) v1(217.43,2.29) v1(218.18,9.04) v1(218.18,8.29) v1(218.18,7.54) v1(218.18,6.79) v1(218.18,6.04) v1(218.18,5.29) v1(218.18,4.54) v1(218.18,3.79) v1(218.18,3.04) v1(218.18,2.29) v1(218.93,9.04) v1(218.93,8.29) v1(218.93,7.54) v1(218.93,6.79) v1(218.93,6.04) v1(218.93,5.29) v1(218.93,4.54) v1(218.93,3.79) v1(218.93,3.04) v1(218.93,2.29) v1(219.68,9.04) v1(219.68,8.29) v1(219.68,7.54) v1(219.68,6.79) v1(219.68,6.04) v1(219.68,5.29) v1(219.68,4.54) v1(219.68,3.79) v1(219.68,3.04) v1(219.68,2.29) v1(220.42,9.06) v1(220.42,8.31) v1(220.42,7.56) v1(220.42,6.81) v1(220.42,6.06) v1(220.42,5.31) v1(220.42,4.56) v1(220.42,3.81) v1(220.42,3.06) v1(220.42,2.31) v1(221.17,9.06) v1(221.17,8.31) v1(221.17,7.56) v1(221.17,6.81) v1(221.17,6.06) v1(221.17,5.31) v1(221.17,4.56) v1(221.17,3.81) v1(221.17,3.06) v1(221.17,2.31) v1(221.92,9.06) v1(221.92,8.31) v1(221.92,7.56) v1(221.92,6.81) v1(221.92,6.06) v1(221.92,5.31) v1(221.92,4.56) v1(221.92,3.81) v1(221.92,3.06) v1(221.92,2.31) v1(222.67,9.06) v1(222.67,8.31) v1(222.67,7.56) v1(222.67,6.81) v1(222.67,6.06) v1(222.67,5.31) v1(222.67,4.56) v1(222.67,3.81) v1(222.67,3.06) v1(222.67,2.31) v1(223.42,9.06) v1(223.42,8.31) v1(223.42,7.56) v1(223.42,6.81) v1(223.42,6.06) v1(223.42,5.31) v1(223.42,4.56) v1(223.42,3.81) v1(223.42,3.06) v1(223.42,2.31) v1(224.17,9.06) v1(224.17,8.31) v1(224.17,7.56) v1(224.17,6.81) v1(224.17,6.06) v1(224.17,5.31) v1(224.17,4.56) v1(224.17,3.81) v1(224.17,3.06) v1(224.17,2.31) v1(224.92,9.04) v1(224.92,8.29) v1(224.92,7.54) v1(224.92,6.79) v1(224.92,6.04) v1(224.92,5.29) v1(224.92,4.54) v1(224.92,3.79) v1(224.92,3.04) v1(224.92,2.29) v1(225.67,9.04) v1(225.67,8.29) v1(225.67,7.54) v1(225.67,6.79) v1(225.67,6.04) v1(225.67,5.29) v1(225.67,4.54) v1(225.67,3.79) v1(225.67,3.04) v1(225.67,2.29) v1(226.42,9.04) v1(226.42,8.29) v1(226.42,7.54) v1(226.42,6.79) v1(226.42,6.04) v1(226.42,5.29) v1(226.42,4.54) v1(226.42,3.79) v1(226.42,3.04) v1(226.42,2.29) v1(227.17,9.04) v1(227.17,8.29) v1(227.17,7.54) v1(227.17,6.79) v1(227.17,6.04) v1(227.17,5.29) v1(227.17,4.54) v1(227.17,3.79) v1(227.17,3.04) v1(227.17,2.29) v1(227.92,7.54) v1(227.92,6.79) v1(227.92,6.04) v1(227.92,5.29) v1(227.92,4.54) v1(227.92,3.79) v1(227.92,3.04) v1(227.92,2.29) v1(228.67,7.54) v1(228.67,6.79) v1(228.67,6.04) v1(228.67,5.29) v1(228.67,4.54) v1(228.67,3.79) v1(228.67,3.04) v1(228.67,2.29) v1(229.44,7.54) v1(229.44,6.79) v1(229.44,6.04) v1(229.44,5.29) v1(229.44,4.54) v1(229.44,3.79) v1(229.44,3.04) v1(229.44,2.29) v1(230.19,7.54) v1(230.19,6.79) v1(230.19,6.04) v1(230.19,5.29) v1(230.19,4.54) v1(230.19,3.79) v1(230.19,3.04) v1(230.19,2.29) v1(230.94,5.29) v1(230.94,4.54) v1(230.94,3.79) v1(230.94,3.04) v1(230.94,2.29) v1(231.69,5.29) v1(231.69,4.54) v1(231.69,3.79) v1(231.69,3.04) v1(231.69,2.29) v1(232.44,5.29) v1(232.44,4.54) v1(232.44,3.79) v1(232.44,3.04) v1(232.44,2.29) v1(233.19,5.29) v1(233.19,4.54) v1(233.19,3.79) v1(233.19,3.04) v1(233.19,2.29) v1(233.91,5.28) v1(233.91,4.53) v1(233.91,3.78) v1(233.91,3.03) v1(233.91,2.28) v1(234.66,5.28) v1(234.66,4.53) v1(234.66,3.78) v1(234.66,3.03) v1(234.66,2.28) v1(235.41,5.28) v1(235.41,4.53) v1(235.41,3.78) v1(235.41,3.03) v1(235.41,2.28) v1(236.16,5.28) v1(236.16,4.53) v1(236.16,3.78) v1(236.16,3.03) v1(236.16,2.28) v1(236.91,5.28) v1(236.91,4.53) v1(236.91,3.78) v1(236.91,3.03) v1(236.91,2.28) v1(237.66,5.28) v1(237.66,4.53) v1(237.66,3.78) v1(237.66,3.03) v1(237.66,2.28) v1(238.41,5.28) v1(238.41,4.53) v1(238.41,3.78) v1(238.41,3.03) v1(238.41,2.28) v1(239.16,5.28) v1(239.16,4.53) v1(239.16,3.78) v1(239.16,3.03) v1(239.16,2.28)
N13422446: length 55.6
  TOP w0.508: v1(176,12.9) 176,15.75 177.32,17.07 220.62,17.07 v1(221.13,16.56) v1(226.54,16.56)
  BOTTOM w0.254: U3.5 174.96,12.98
  BOTTOM w0.305: 174.96,12.98 175.92,12.98 v1(176,12.9)
N13423706: length 7.7
  TOP w0.508: v1(151.82,3.53) 151.82,4.8 152.78,5.77 156.95,5.77 157.15,5.97 v1(157.73,5.97)
N13449363: length 2.5
  BOTTOM w0.508: T2.6 155.57,6.31 155.57,6.11
N13513324: length 127
  TOP w0.508: v1(174.75,17.7) 175.6,18.55 231.13,18.55 234.31,15.37 234.34,15.37 v1(235.08,14.63)
  BOTTOM w0.508: 192.76,1.07 193.45,0.38 240.89,0.38 241.88,1.37 241.88,12.65 244.38,15.14 ; 240.46,18.67 R31.2
N13523750: length 52.7
  TOP w0.305: v1(162.76,0.64) 162.39,0.26 112.18,0.26 v1(111.79,0.66)
  BOTTOM w0.305: R20.2 111.79,1.8 v1(111.79,0.66)
N13967710: length 13
  BOTTOM w0.381: R11.1 77.57,9.27 76.1,10.74 76.1,13.16 74.9,14.36 U2.6 71.09,14.36 C9.1
  BOTTOM w0.508: R12.2 C9.1
N13967734: length 18.8
  TOP w0.381: v1(73.84,15.82) 73.84,12.79 73.85,12.78 v1(73.85,12.11)
  BOTTOM w0.254: v1(73.84,15.82) 73.86,15.82
  BOTTOM w0.305: U2.3 v1(73.85,12.11) ; C6.1 66.98,20.12 67.46,20.6 73.53,20.6 74.04,20.09 74.04,16.03 v1(73.84,15.82) 73.82,15.81 72.7,15.81 U2.8
N13967764: length 12.7
  BOTTOM w0.254: C7.1 65.13,17.09 65.38,16.84 65.38,16.43 R8.1 65.53,16.03 64.9,16.03 64.64,15.77 64.64,14.61 65.15,14.1 67.3,14.1 67.79,13.61 U2.5
N13967788: length 6.3
  BOTTOM w0.381: R6.2 75.06,12.47 74.62,12.91 73.75,12.91 73.73,12.89 73.49,12.89 73.47,12.86 U2.4
N13967858: length 5.2
  TOP w0.508: v1(67.59,11.38) 67.59,12.12 67.82,12.34 v1(67.82,16.51)
N13971397:
  vias: v1(76.13,24.43) v1(76.13,23.68) v1(76.13,22.93) v1(76.13,22.18) v1(76.13,21.43) v1(76.13,20.68) v1(76.13,19.93) v1(76.88,24.43) v1(76.88,23.68) v1(76.88,22.93) v1(76.88,22.18) v1(76.88,21.43) v1(76.88,20.68) v1(76.88,19.93) v1(77.63,24.43) v1(77.63,23.68) v1(77.63,22.93) v1(77.63,22.18) v1(77.63,21.43) v1(77.63,20.68) v1(77.63,19.93) v1(77.81,19.07) v1(77.81,18.32) v1(77.81,17.57) v1(77.81,16.82) v1(77.81,16.07) v1(77.81,15.32) v1(77.81,14.57) v1(78.57,19.07) v1(78.57,18.32) v1(78.57,17.57) v1(78.57,16.82) v1(78.57,16.07) v1(78.57,15.32) v1(78.57,14.57) v1(78.82,24.43) v1(78.82,23.68) v1(79.32,19.07) v1(79.32,18.32) v1(79.32,17.57) v1(79.32,16.82) v1(79.32,16.07) v1(79.32,15.32) v1(79.32,14.57) v1(79.57,24.43) v1(79.57,23.68) v1(80.07,19.07) v1(80.07,18.32) v1(80.07,17.57) v1(80.07,16.82) v1(80.07,16.07) v1(80.07,15.32) v1(80.07,14.57) v1(80.32,24.43) v1(80.32,23.68) v1(80.82,19.07) v1(80.82,18.32) v1(80.82,17.57) v1(80.82,16.82) v1(80.82,16.07) v1(80.82,15.32) v1(80.82,14.57) v1(81.07,24.43) v1(81.07,23.68) v1(81.57,19.07) v1(81.57,18.32) v1(81.57,17.57) v1(81.57,16.82) v1(81.57,16.07) v1(81.57,15.32) v1(81.57,14.57) v1(81.82,24.43) v1(81.82,23.68) v1(82.32,19.07) v1(82.32,18.32) v1(82.32,17.57) v1(82.32,16.82) v1(82.32,16.07) v1(82.32,15.32) v1(82.32,14.57) v1(82.57,24.43) v1(82.57,23.68) v1(83.07,19.07) v1(83.07,18.32) v1(83.07,17.57) v1(83.07,16.82) v1(83.07,16.07) v1(83.07,15.32) v1(83.07,14.57) v1(83.32,24.43) v1(83.32,23.68) v1(83.82,19.07) v1(83.82,18.32) v1(83.82,17.57) v1(83.82,16.82) v1(83.82,16.07) v1(83.82,15.32) v1(83.82,14.57) v1(84.07,24.43) v1(84.07,23.68) v1(84.82,24.43) v1(84.82,23.68) v1(85.57,24.43) v1(85.57,23.68) v1(86.72,15.93) v1(86.72,15.18) v1(86.72,14.43) v1(87.47,15.93) v1(87.47,15.18) v1(87.47,14.43) v1(87.74,24.02) v1(87.74,23.27) v1(87.74,22.52) v1(87.74,21.77) v1(87.74,21.02) v1(87.74,20.27) v1(87.74,19.52) v1(87.74,18.77) v1(88.22,15.93) v1(88.22,15.18) v1(88.22,14.43) v1(88.49,24.02) v1(88.49,23.27) v1(88.49,22.52) v1(88.49,21.77) v1(88.49,21.02) v1(88.49,20.27) v1(88.49,19.52) v1(88.49,18.77) v1(89.24,24.02) v1(89.24,23.27) v1(89.24,22.52) v1(89.24,21.77) v1(89.24,21.02) v1(89.24,20.27) v1(89.24,19.52) v1(89.24,18.77) v1(89.24,18.02) v1(89.24,17.27) v1(89.24,16.52) v1(89.24,15.77) v1(89.99,24.02) v1(89.99,23.27) v1(89.99,22.52) v1(89.99,21.77) v1(89.99,21.02) v1(89.99,20.27) v1(89.99,19.52) v1(89.99,18.77) v1(89.99,18.02) v1(89.99,17.27) v1(89.99,16.52) v1(89.99,15.77) v1(90.74,24.02) v1(90.74,23.27) v1(90.74,22.52) v1(90.74,21.77) v1(90.74,21.02) v1(90.74,20.27) v1(90.74,19.52) v1(90.74,18.77) v1(90.74,18.02) v1(90.74,17.27) v1(90.74,16.52) v1(90.74,15.77) v1(91.49,24.02) v1(91.49,23.27) v1(91.49,22.52) v1(91.49,21.77) v1(91.49,21.02) v1(91.49,20.27) v1(91.49,19.52) v1(91.49,18.77) v1(91.49,18.02) v1(91.49,17.27) v1(91.49,16.52) v1(91.49,15.77) v1(92.24,24.02) v1(92.24,23.27) v1(92.24,22.52) v1(92.24,21.77) v1(92.24,21.02) v1(92.24,20.27) v1(92.24,19.52) v1(92.24,18.77) v1(92.24,18.02) v1(92.24,17.27) v1(92.24,16.52) v1(92.24,15.77) v1(92.99,24.02) v1(92.99,23.27) v1(92.99,22.52) v1(92.99,21.77) v1(92.99,21.02) v1(92.99,20.27) v1(92.99,19.52) v1(92.99,18.77) v1(92.99,18.02) v1(92.99,17.27) v1(92.99,16.52) v1(93.74,24.02) v1(93.74,23.27) v1(93.74,22.52) v1(93.74,21.77) v1(93.74,21.02) v1(93.74,20.27) v1(93.74,19.52) v1(93.74,18.77) v1(93.74,18.02) v1(93.74,17.27) v1(94.49,24.02) v1(94.49,23.27) v1(94.49,22.52) v1(94.49,21.77) v1(94.49,21.02) v1(94.49,20.27) v1(94.49,19.52) v1(94.49,18.77) v1(94.49,18.02) v1(94.49,17.27)

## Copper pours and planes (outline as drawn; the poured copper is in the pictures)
GND on BOTTOM (solid shape): 220.04,14.83 217.12,14.83 217.12,15.75 220.04,15.75
GND on BOTTOM (solid shape): 225.48,14.81 222.55,14.81 222.55,15.72 225.48,15.72
GND on TOP: 224.97,22.96 226.19,22.96 226.52,22.63 226.52,21.64 226.31,21.44 224.79,21.44 224.64,21.59 224.64,22.63
GND on TOP: 235.08,22.91 235.08,22 235.74,21.34 236.93,21.34 237.59,22 237.59,22.96 237.29,23.27 235.43,23.27
GND on BOTTOM: outline of 89 points within 173.79,14.08 241.76,25.04
GND on BOTTOM: 196.11,8.18 196.11,7.04 196.04,6.96 196.04,4.5 196.42,4.11 197.89,4.11 199.01,5.23 199.01,20.85 197.49,22.38 182.45,22.38 178.1,18.03 178.1,16.92 178.51,16.51 179.83,17.83 179.83,18.36 183.06,21.59 196.6,21.59 198.2,19.99 198.2,7.19 197.49,6.48 197.49,8.1 197.33,8.26 196.19,8.26
VCCP on TOP: 158.12,4.95 158.14,4.93 158.14,3.63 156.08,3.63 155.94,3.77 155.94,4.56 156.34,4.95
VCCP on BOTTOM: 81.48,7.24 83.92,7.24 88.77,2.39 90.07,2.39 90.75,1.7 90.75,1.35 90.63,1.22 88.8,1.22 83.52,6.5 81.64,6.5 81.43,6.71 81.43,7.19
VCCP on BOTTOM: 65.81,7.21 65.81,6.32 65.94,6.2 69.67,6.2 70.05,6.58 70.05,7.04 69.57,7.52 68.45,7.52 68.12,7.19 65.84,7.19
VCCP on BOTTOM: 153.11,2.74 153.26,2.9 154.31,2.9 154.89,3.48 154.89,4.83 155.09,5.03 158.32,5.03 158.7,4.65 160.02,4.65 160.02,3.84 158.52,3.84 158.2,3.52 156.63,3.52 156.39,3.28 156.39,2.49 155.88,1.98 151.18,1.98 151.1,2.06 151.1,2.72 151.13,2.74
BPS on BOTTOM: 193.62,14.56 193.91,14.86 195.2,14.86 195.22,14.88 195.22,15.65 195.15,15.72 192.68,15.72 192.33,15.37 192.33,14.88 192.65,14.56
BPS on BOTTOM: 173.86,13.92 176.5,13.92 176.78,14.2 178.16,14.2 178.31,14.05 178.31,12.19 178.16,12.04 177.67,12.04 176.76,12.95 176.76,13.34 176.56,13.54 173.89,13.54 173.79,13.64 173.79,13.84
N13420620 on BOTTOM (solid shape): 100.61,9.4 100.61,7.42 100.13,6.93 96.04,6.93 95.43,7.54 95.43,9.45 95.68,9.7 100.3,9.7
N13420620 on TOP: 158.12,24.74 158.45,24.41 158.45,21.62 158.31,21.48 154.17,21.48 154.04,21.35 150.2,21.35 149.35,22.2 119.33,22.2 114.91,17.78 114.91,7.54 112.45,5.08 108.1,5.08 108.1,7.21 110.74,7.21 112.93,9.4 112.93,20.42 117.25,24.74
N13420620 on BOTTOM: 94.97,9.22 95.45,9.7 103.45,9.7 103.47,9.69 104.81,9.69 106.43,8.08 110.82,8.08 112.6,6.3 112.6,4.32 108.86,4.32 105.71,1.17 99.16,1.17 98.93,1.4 98.93,4.9 98.03,5.8 93.66,5.8 91.95,7.52 91.8,7.52 91.67,7.65 91.67,9.19 91.69,9.22
N13420620 on BOTTOM: 82.52,1.17 83.57,0.13 86.03,0.13 86.26,0.36 86.26,0.91 84.61,2.57 84.61,2.59 83.95,3.25 82.52,3.25
N13420620 on BOTTOM: 162.71,22.63 162.71,20.55 162.46,20.29 160.45,20.29 159.13,21.62 154.18,21.62 153.9,21.34 151.97,21.34 151.83,21.48 151.83,22.78 151.01,23.6 140.9,23.6 139.93,22.63 135.48,22.63 135.48,24.82 135.81,25.15 160.2,25.15
N13420648 on TOP: 159.92,3.58 158.83,4.67 158.83,6.2 158.84,6.21 158.84,8.66 158.18,9.32 156.31,9.32 155.75,8.76 155.75,8.74 155.63,8.61 155.63,6.93 155.37,6.68 152.15,6.68 150.98,5.51 150.98,3.48 149.69,2.2 116.22,2.2 115.42,3 115.42,5.37 116.5,6.45 116.5,17.06 119.91,20.47 145.59,20.47 145.64,20.42 147.6,20.42 149.09,18.94 153.35,18.94 153.94,18.35 153.94,16.13 155.72,14.34 159.05,14.34 160.22,15.52 160.22,19.08 160.63,19.48 164.44,19.48 165.07,18.85 165.07,3.86 164.8,3.58
N13420648 on TOP: 71.65,24.99 72.19,24.46 72.19,11.81 72.96,11.04 74.98,11.04 76.62,12.67 93.46,12.67 97.97,17.18 97.97,23.44 99.16,24.64 109.78,24.64 110.34,24.08 110.34,12.29 110.6,12.03 110.6,10.33 109.87,9.59 107.25,9.59 105.92,8.26 105.92,3.76 104.98,2.82 91.74,2.82 91.14,3.43 91.14,8.51 89.31,10.34 85.9,10.34 83.59,8.03 70.66,8.03 69.39,9.3 69.39,17.02 69.04,17.37 66.85,17.37 65.91,16.43 65.91,12.95 65.15,12.19 62.69,12.19 61.7,13.18 61.7,23.52 61.73,23.56 61.73,24.6 62.13,24.99
N13420648 on TOP: 183.54,0.1 164.95,0.1 163.53,1.52 157.28,1.52 156.77,2.03 156.77,2.67 157.02,2.92 165.15,2.92 166.98,1.09 180.02,1.09 181.43,2.5 182.61,3.68 183.55,3.68 183.82,3.4 183.82,0.38
N13420648 on BOTTOM: 68.25,19.28 68.25,17.96 68.5,17.7 69.95,17.7 70.26,18.01 70.26,19.84 70.13,19.96 68.94,19.96
N13420648 on BOTTOM: 84.73,10.82 89.18,10.82 90.98,12.62 94.11,12.62 94.16,12.57 94.16,11.02 94.13,11 92.02,11 90.86,9.83 90.86,9.8 89.84,9.8 89.33,10.31 84.89,10.31 84.71,10.49 84.71,10.59 84.76,10.64 84.76,10.79
N13420648 on BOTTOM: 184.38,3.38 184.38,0.3 184.15,0.08 180.67,0.08 180.49,0.25 180.49,1.3 182.58,3.38
N13420648 on BOTTOM: 164.68,9.03 164.69,9.04 164.69,13.72 164.44,13.97 156.29,13.97 153.95,16.31 153.92,16.31 153.25,16.98 135.29,16.98 134.52,17.75 134.52,24.13 133.88,24.77 106.35,24.77 105.97,24.38 105.97,11.58 107.72,9.83 111.51,9.83 114.96,6.38 114.96,1.4 116.26,0.1 157.96,0.1 158.19,0.33 158.19,2.57 157.81,2.95 157.1,2.95 156.79,2.64 156.79,1.88 156.3,1.38 148.88,1.38 148.46,1.81 148.46,7.42 149.12,8.08 155.19,8.08 156.41,9.3 158.06,9.3 158.34,9.03
N13420648 on BOTTOM: 61.98,14.33 63.88,14.33 64.49,13.72 64.49,12.57 64.26,12.34 62.43,12.34 61.7,13.08 61.7,14.05
N13420656 on TOP: 214.66,12.65 213.03,12.65 211.84,13.84 211.84,15.16 212.06,15.39 215.24,15.39 215.57,15.06 215.57,13.56
N13420656 on TOP: 219.81,24.41 220.55,25.15 231.04,25.15 233.96,22.23 233.96,21.77 235.52,20.21 235.98,20.21 244.75,11.43 246.53,11.43 246.94,11.02 246.94,8.59 246.74,8.38 243.15,8.38 230.61,20.93 230.61,21.59 230.35,21.84 228.6,21.84 227.05,23.39 224.31,23.39 222.25,21.34 219.86,21.34 219.81,21.39
N13420656 on BOTTOM: 230.15,23.19 232.16,23.19 232.21,23.14 232.21,21.95 231.7,21.44 230.17,21.44 230.07,21.54 230.07,23.11
N13420656 on BOTTOM: 221.39,21.41 217.07,21.41 215.57,19.91 215.57,13 215.01,12.45 212.6,12.45 211.58,11.43 211.56,11.43 211.23,11.1 211.23,11.05 202.13,1.96 192.81,1.96 192.61,2.16 192.61,3.3 192.79,3.48 193.4,3.48 194.11,2.77 200.9,2.77 210.29,12.15 210.3,12.15 213.08,14.94 213.08,20.85 215.24,23.01 221.4,23.01 221.39,23
N13420656 on BOTTOM: 173.86,12.42 175.59,12.42 175.72,12.29 176.96,12.29 177.56,11.7 178.98,11.7 179.15,11.86 180.01,11.86 180.06,11.81 180.06,11.53 180.23,11.37 182.46,11.37 182.88,11.79 183.95,11.79 184.38,12.22 184.38,13.44 184.07,13.74 183.11,13.74 182.91,13.94 182.91,16.61 182.98,16.69 184.61,16.69 185.12,17.2 185.12,19.25 186.82,20.95 187.17,20.95 187.66,20.47 187.66,20.12 186.03,18.49 186.03,13.23 183.97,11.18 183.21,11.18 183.01,10.97 178.92,10.97 178.52,11.37 177.28,11.37 176.63,12.01 173.89,12.01 173.79,12.12 173.79,12.34
N13420656 on BOTTOM: 243.4,7.86 243.66,7.59 246.63,7.59 246.94,7.9 246.94,12.04 246.81,12.17 242.85,12.17 242.75,12.06 242.75,10.74 243.4,10.1
N13421012 on BOTTOM: 173.86,14.68 178.97,14.68 178.99,14.66 178.99,14.17 178.97,14.15 178.82,14.15 178.46,14.5 176.38,14.5 176.15,14.27 173.89,14.27 173.81,14.35 173.81,14.63
N13421012 on BOTTOM: 181.99,13.28 180.52,13.28 180.06,12.83 180.06,12.42 179.07,12.42 179.07,13.89 178.71,14.25 178.71,14.68 179.02,14.99 180.8,14.99 180.95,15.14 180.95,15.85 181,15.9 181.79,15.9 181.98,15.71 181.98,14.95 181.99,14.94
N13421042 on BOTTOM: 180.97,11.86 180.97,12.62 181.03,12.67 181.94,12.67 182.07,12.8 182.42,12.8 182.73,13.11 183.82,13.11 183.87,13.06 183.87,12.27 182.35,12.27 181.94,11.86
N13421702 on BOTTOM: 239.75,9.02 231.29,9.02 231.09,9.22 231.09,13.23 231.11,13.26 238.81,13.26 239.75,12.32
N13421894 on BOTTOM (solid shape): 221.31,9.75 217.09,9.75 217.09,13.79 221.31,13.79
N13421894 on BOTTOM (solid shape): 226.75,9.73 222.53,9.73 222.53,13.77 226.75,13.77
N13421894 on TOP: 212.67,9.12 212.67,1.22 213.33,0.56 239.73,0.56 240.39,1.22 240.39,7.8 236.68,11.51 236.65,11.51 234.39,13.77 217.22,13.77 216.69,13.23 216.69,12.42 215.52,11.25 213.33,11.25 212.72,10.64 212.72,9.17
N13421894 on BOTTOM: 216.69,12.42 216.69,13.72 216.71,13.74 226.72,13.74 226.72,12.65 227.74,11.63 230.12,11.63 230.17,11.58 230.17,8.84 230.97,8.04 238.01,8.04 238.4,8.43 238.4,8.51 239.75,8.51 240.35,7.91 240.35,1.97 239.93,1.55 213.72,1.55 212.72,2.54 212.72,10.62 213.39,11.28 215.54,11.28
N13421894 on BOTTOM: 176.2,8.66 176.2,9.45 176.23,9.47 177.19,9.47 178.03,10.31 178.51,10.31 178.63,10.2 178.63,9.66 178.44,9.47 177.93,9.47 177.11,8.66
N13422446 on BOTTOM: 226.21,16.76 226.21,14.99 226.34,14.86 226.77,14.86 226.85,14.94 226.85,16.71 226.67,16.89 226.34,16.89
N13422446 on BOTTOM: 173.81,13.18 175.84,13.18 175.9,13.23 176.28,13.23 176.39,13.12 176.39,12.71 176.28,12.6 175.84,12.6 175.67,12.78 173.81,12.78 173.79,12.8 173.79,13.16
N13422446 on BOTTOM: 220.8,16.89 220.8,14.96 220.88,14.88 221.44,14.88 221.46,14.91 221.46,16.61 221.45,16.62 221.45,16.93 221.39,16.99 220.9,16.99
N13423706 on BOTTOM: 157.63,6.27 158.7,6.27 159.36,6.93 159.36,8.26 159.77,8.66 162.59,8.66 162.61,8.64 162.61,8.28 160.91,8.28 160.6,7.98 160.6,5.41 160.45,5.26 158.98,5.26 158.66,5.58 157.77,5.58 157.51,5.84 157.51,6.15
N13423706 on BOTTOM: 150.18,2.88 151.1,3.81 151.99,3.81 152.1,3.71 152.1,3.33 151.99,3.23 151.03,3.23 150.27,2.46 150.27,2.06 150.22,2.01 149.4,2.01 149.28,2.13 149.28,2.79 149.36,2.88
N13423710 on BOTTOM: 193.83,6.2 193.04,6.99 192.51,6.99 192.43,7.06 192.43,7.75 192.46,7.77 193.98,7.77 194.11,7.9 195.28,7.9 195.38,7.8 195.38,4.72 194.82,4.17 194.34,4.17 193.83,4.67
N13423714 on BOTTOM: 193.95,8.59 193.95,11.33 193.62,11.66 192.61,11.66 192.46,11.81 192.46,12.34 196.98,12.34 197.33,11.99 197.33,9.12 197.31,9.09 195.99,9.09 195.3,8.41 194.13,8.41
N13440082 on BOTTOM: 194.26,14.12 194.26,13.39 194.23,13.36 194.26,13.34 197.36,13.34 197.36,14.4 197.21,14.55 195.94,14.55 195.63,14.25 194.39,14.25
N13449363 on BOTTOM: 156.82,8.89 157.63,8.89 158.17,8.36 158.17,7.37 157.58,6.78 157.25,6.78 156.54,6.07 156.51,6.07 156.34,5.89 154.94,5.89 154.91,5.92 154.91,6.55 154.71,6.76 153.44,6.76 153.31,6.88 153.31,7.54 153.34,7.57 155.5,7.57
N13473411 on BOTTOM: 149.28,5.94 149.28,3.78 149.35,3.71 150.11,3.71 150.32,3.91 150.32,5.84 150.14,6.02 149.35,6.02
N13473415 on BOTTOM: 149.43,7.42 151.61,7.42 152.35,6.68 152.35,4.7 152.22,4.57 151.21,4.57 151.13,4.65 151.13,6.32 150.83,6.63 149.48,6.63 149.35,6.76 149.35,7.34
N13513324 on BOTTOM: 246.51,19.51 247.29,18.72 247.29,13.18 247.04,12.93 242.93,12.93 242.77,13.08 242.77,15.34 241.21,16.9 239.71,16.9 239.55,16.74 239.55,15.72 238,14.17 235.05,14.17 234.78,14.44 234.8,14.45 234.8,14.86 235,15.06 237.67,15.06 238.68,16.08 238.68,16.51 238.12,17.07 237.41,17.07 237.11,17.37 237.11,19.51
N13513324 on BOTTOM: 173.79,15.8 173.79,17.45 174.32,17.98 175.06,17.98 175.34,17.7 175.34,15.77 173.81,15.77
N13515268 on BOTTOM: 153.34,6.02 153.34,3.71 153.44,3.61 154.13,3.61 154.23,3.71 154.23,5.97 154.1,6.1 153.42,6.1
N13515819 on BOTTOM: 192.41,11 192.41,8.51 192.48,8.43 193.34,8.43 193.4,8.48 193.4,10.87 193.27,11
N13523750 on BOTTOM: 162.53,1.3 162.53,0.51 162.69,0.36 163.25,0.36 163.83,0.94 164.85,0.94 164.87,0.97 164.87,2.13 164.82,2.18 164.11,2.18 164.08,2.21 163.45,2.21
N13523750 on BOTTOM: 110.85,2.69 110.85,0.74 111.2,0.38 112.06,0.38 112.32,0.64 112.32,2.51 112.12,2.72 110.87,2.72
N13523772 on BOTTOM: 164.69,4.5 164.9,4.29 164.9,3.12 164.87,3.1 161.7,3.1 161.49,3.3 161.49,4.5
N13523865 on BOTTOM: 162.74,5.44 162.66,5.36 161.62,5.36 161.57,5.41 161.57,5.77 161.52,5.82 161.52,6.99 161.09,7.42 161.09,7.87 161.14,7.92 162.71,7.92 162.74,7.9
N13911889 on BOTTOM: 135.51,19.33 135.51,20.85 139.83,20.85 140.84,21.87 140.84,22.1 141.05,22.3 144.37,22.3 144.48,22.2 144.48,21.03 144.42,20.98 140.79,20.98 139.98,20.17 139.98,19.33
N13911953 on BOTTOM: 141.45,18.36 140.98,18.83 140.98,20.09 144.5,20.09 145.11,20.7 146.15,20.7 146.15,18.9 145.62,18.36
N13912909 on TOP: 156.21,18.49 156.21,16.71 156.77,16.15 157.84,16.15 158.27,16.59 158.27,18.47 157.84,18.9 156.62,18.9
N13912909 on BOTTOM: 149.45,18.78 154.17,18.78 155.96,16.99 155.96,16.97 157.15,15.77 162.61,15.77 162.64,15.8 162.64,18.24 162.33,18.54 160.78,18.54 160.76,18.52 156.29,18.52 154.89,19.91 151.49,19.91 150.57,20.83 149.45,20.83
N13916087 on BOTTOM: 173.84,11.66 176.35,11.66 177.14,10.87 177.14,10.06 176.16,10.06 176.16,10.86 175.74,11.28 173.86,11.28 173.79,11.35 173.79,11.61
N13925544 on TOP: 62.46,6.48 62.46,4.93 62.76,4.62 64.95,4.62 65.38,5.05 65.38,6.88 65.25,7.01 62.99,7.01
N13925544 on BOTTOM: 62.38,4.6 64.34,4.6 64.44,4.7 64.44,6.38 64.06,6.76 62.61,6.76 61.16,8.2 57.02,8.2 56.55,8.67 56.55,12.46 57.81,13.72 57.81,18.72 57,19.53 55.32,19.53 54.25,18.47 54.25,8.26 56.17,6.34 60.64,6.34
N13925608 on TOP: 59.82,11.38 59.84,11.38 60.63,10.59 64.11,10.59 64.39,10.31 64.39,8.66 64.01,8.28 61.93,8.28 60.77,7.12 60.77,3.59 60.74,3.57 60.74,1.28 60.07,0.61 54.25,0.61 53.24,1.63 53.24,10.74 43,20.98 43,22.61 43.64,23.24 44.53,23.24 56.13,11.63 59.59,11.63 59.82,11.4
N13925608 on BOTTOM: 64.08,8.61 62.61,8.61 62.2,9.02 62.2,10.74 62.28,10.82 63.96,10.82 64.54,10.24 64.54,9.07
N13925608 on BOTTOM: 41.3,22.66 41.3,21.13 42.29,20.14 45.09,20.14 45.42,20.47 45.42,23.16 45.11,23.47 42.11,23.47
N13925608 on BOTTOM: 58.14,4.75 58.14,2.77 58.42,2.49 60.22,2.49 60.43,2.69 60.43,4.67 59.94,5.16 58.55,5.16
N13925608 on BOTTOM: 60.05,11.91 60.33,11.63 60.33,9.93 59.82,9.42 58.5,9.42 58.04,9.88 58.04,10.72 58.05,10.73 58.05,11.67 58.29,11.91
N13925722 on BOTTOM: 49.53,1.5 51.87,3.84 51.87,20.24 53.62,21.98 55.36,21.98 55.6,21.74 55.6,21.31 57.02,21.31 57.02,21.79 57.48,22.25 57.48,22.28 58.09,22.89 58.09,24.84 57.86,25.07 49.78,25.07 48.18,23.47 48.18,12.85 43.87,8.53 43.87,6.43 40.92,3.48 40.92,1.7 41.12,1.5
N13925782 on BOTTOM: 22.25,12.04 22.25,3.86 25.45,0.66 37.92,0.66 38.96,1.7 38.96,3.17 37.44,4.7 37.44,7.47 36.2,7.47 36.17,7.44 36.07,7.54 28.91,7.54 23.95,12.5 22.71,12.5
N13925794 on BOTTOM: 22.15,21.26 22.19,21.3 22.19,22.92 23.34,24.08 34.47,24.08 34.49,24.05 37.82,24.05 39.22,22.66 39.22,21.18 37.48,19.44 37.48,17.69 37.29,17.5 33.66,17.5 33.66,17.45 33.64,17.44 33.63,17.45 28.07,17.45 27.38,16.76 25.07,16.76 23.47,15.16 22.5,15.16 22.15,15.52
N13925904 on BOTTOM (solid shape): 30.94,10.93 30.94,10.42 34.14,10.41 34.14,10.92 34.75,10.92 34.75,8.74 30.33,8.74 30.33,10.93
N13925904 on BOTTOM: 33.99,11.05 37.21,11.05 37.49,10.77 37.49,9.32 36.91,8.74 33.55,8.74 33.54,8.72 30.02,8.72 30.02,10.92 30.1,11 33.93,11
N13925908 on BOTTOM (solid shape): 34.73,16.13 34.73,13.94 34.12,13.95 34.12,14.45 30.92,14.46 30.92,13.95 30.31,13.95 30.31,16.14
N13925908 on BOTTOM: 35.64,13.23 35.15,13.72 30.18,13.72 30.18,15.95 30.38,16.15 37.49,16.15 37.59,16.05 37.59,13.49 37.34,13.23
N13925956 on BOTTOM: 11.38,12.19 14.81,12.19 16.43,13.82 18.31,13.82 18.9,13.23 18.9,5.49 18.26,4.85 16.76,4.85 16.28,5.33 16.28,8.59 15.06,9.8 11.56,9.8 11.05,10.31 11.05,11.86
N13925960 on BOTTOM: 3,15.72 5.31,18.03 12.52,18.03 15.04,20.55 16.36,20.55 19.08,17.83 19.08,15.82 18.62,15.37 17.17,15.37 17.07,15.47 8.66,15.47 6.48,13.28 3.68,13.28 3,13.97
N13926028 on BOTTOM: 3.3,7.67 3.3,5.23 3.91,4.62 13.08,4.62 13.36,4.9 13.36,6.65 12.95,7.06 6.48,7.06 5.51,8.03 3.66,8.03
N13967468 on TOP: 87.02,0.15 88.9,2.03 88.9,8.23 88,9.13 87.24,9.13 83.53,5.42 67.93,5.42 65.71,3.2 62.69,3.2 62.46,2.97 62.46,0.51 62.81,0.15
N13967468 on BOTTOM: 86.72,8.64 86.72,6.96 90.35,3.33 91.06,3.33 92.43,1.96 95.73,1.96 96.16,2.39 96.16,4.32 95.78,4.7 92.81,4.7 88.34,9.17 87.25,9.17
N13967468 on BOTTOM: 69.76,4.81 70.18,4.39 70.18,3.07 70.82,2.44 72.39,2.44 72.59,2.24 72.59,0.18 72.49,0.08 62.76,0.08 62.51,0.33 62.51,3.02 62.66,3.17 67.02,3.17 68.66,4.81
N13967702 on BOTTOM: 77.04,3.05 78.82,3.05 79.02,3.25 80.62,3.25 80.7,3.17 80.7,1.5 76.99,1.5 76.96,1.52 76.96,1.7 76.91,1.75 76.91,2.92
N13967706 on BOTTOM: 71.07,5.74 71.07,4.11 71.27,3.91 72.42,3.91 74.17,2.16 74.17,1.57 75.67,1.57 75.69,1.6 75.69,2.87 75.59,2.97 74.07,2.97 72.77,4.27 72.77,5.51 72.49,5.79 71.12,5.79
N13967710 on BOTTOM: 76.75,8.14 76.86,8.03 78.21,8.03 78.26,8.08 78.26,9.35 77.65,9.96 76.78,9.96 76.64,9.82 76.64,9.74 76.75,9.64
N13967710 on BOTTOM: 68.35,15.19 71.12,15.19 71.2,15.11 71.2,14.66 71.27,14.58 71.27,14.17 68.48,14.17 68.25,14.4 68.25,15.09
N13967734 on BOTTOM: 71.83,16.05 73.53,16.05 73.66,16.18 74.14,16.18 74.24,16.08 74.24,15.7 74.07,15.52 73.69,15.52 73.56,15.65 71.83,15.65 71.78,15.7 71.78,16
N13967734 on BOTTOM: 71.81,12.34 73.63,12.34 73.71,12.42 74.12,12.42 74.19,12.34 74.19,11.89 74.12,11.81 73.58,11.81 73.51,11.89 71.81,11.89 71.78,11.91 71.78,12.32
N13967734 on BOTTOM: 66.5,18.92 66.5,20.17 66.65,20.32 67.26,20.32 67.46,20.12 67.46,18.92
N13967764 on BOTTOM: 65.94,15.85 65.94,17.04 65.66,17.32 65.66,18.24 65.58,18.31 64.67,18.31 64.67,16.1 64.92,15.85
N13967780 on BOTTOM: 74.42,7.29 75.64,7.29 75.67,7.26 75.67,3.81 75.64,3.78 74.45,3.78 74.42,3.81
N13967788 on BOTTOM: 74.27,9.78 74.27,8.2 74.4,8.08 75.69,8.08 75.72,8.1 75.72,9.6 75.26,10.06 74.9,10.06 74.88,10.08 74.57,10.08
N13967788 on BOTTOM: 68.05,13.08 73.51,13.08 73.51,12.65 71.09,12.65 70.79,12.34 70.79,12.24 68.02,12.24 67.97,12.29 67.97,13
N13967796 on BOTTOM: 76.89,7.24 76.89,3.81 76.91,3.78 78.18,3.78 78.18,7.19 78.13,7.24
N13967854 on BOTTOM: 71.78,10.82 73.53,10.82 73.56,10.79 73.56,10.31 73.44,10.2 73.44,8.27 72.9,7.72 70.1,7.72 69.44,8.38 69.44,9.65 69.49,9.7 70.26,9.7 70.33,9.63 70.33,8.79 70.66,8.46 72.06,8.46 72.44,8.84 72.44,10.16 72.24,10.36 71.81,10.36 71.78,10.39
N13967858 on BOTTOM: 72.87,11.58 71.55,11.58 71.48,11.66 70.82,11.66 70.76,11.61 67.69,11.61 67.18,12.12 67.18,12.67 67.03,12.83 65.79,12.83 65.79,12.09 67.13,10.74 69.95,10.74 71.02,9.68 71.02,8.99 71.07,8.94 71.88,8.94 71.88,9.86 71.83,9.91 71.45,9.91 71.06,10.3 71.06,10.96 71.15,11.05 71.7,11.05 71.78,11.13 72.82,11.13 72.9,11.2 72.9,11.56
N13967858 on BOTTOM: 71.07,15.8 71.25,15.98 71.25,18.34 71.55,18.64 73.43,18.64 73.48,18.69 73.48,19.08 71.09,19.08 70.87,18.85 70.87,17.68 70.32,17.13 67.73,17.13 67.55,17.31 67.55,18.15 67.39,18.31 66.57,18.31 65.86,19.02 65.86,19.48 65.61,19.74 64.64,19.74 64.62,19.71 64.62,18.87 64.67,18.82 65.56,18.82 66.42,17.96 66.42,17.35 66.57,17.2 66.57,15.95 66.73,15.8
N13968000 on BOTTOM: 65.38,15.42 67.34,15.42 67.36,15.39 67.36,14.76 67.34,14.73 65.43,14.73 65.35,14.81 65.35,15.39
N13968020 on BOTTOM: 65.68,10.16 65.68,7.95 65.84,7.8 67.54,7.8 68.4,8.66 68.4,9.63 67.84,10.19 66.57,10.19 66.55,10.21 65.74,10.21
N13971397 on BOTTOM (solid shape): 100.43,11.76 95.43,11.76 95.43,15.29 100.43,15.29
N13971397 on BOTTOM (solid shape): 84.4,16.63 86.2,16.63 86.2,13.93 84.54,13.93 84.54,11.98 84.44,11.98 83.52,11.6 83.14,10.68 83.14,10.58 80.59,10.58 80.59,18.88 84.4,18.88
